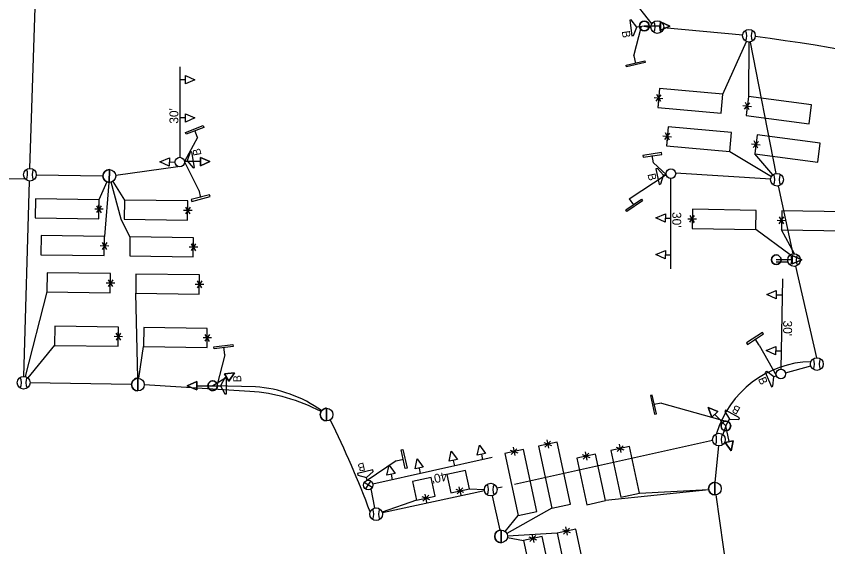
# Model space of a CAD drawing. Extents: x 596176 to 605330, y 332416 to 402398.
# Drawn here: x 604629.8 to 604885.3, y 339247.6 to 339414.6 of the extents above; entities that cross this region are included whole.
import ezdxf

# ---------------------------------------------------------------- set-up
doc = ezdxf.new("R2010")
doc.units = 0
for name, color, linetype in [('P_SIG', 7, 'Continuous'), ('P_SIG_Bold', 7, 'Continuous'), ('P_SIG_Conduit', 7, 'Continuous'), ('P_SIG_Loops', 7, 'Continuous'), ('P_SIG_SignalHeads', 7, 'Continuous')]:
    doc.layers.add(name, color=color, linetype=linetype)

# ---------------------------------------------------------------- blocks, each defined once
blk = doc.blocks.new('SIGNAL HEADS and POLES')
at = {"layer": 'P_SIG'}
blk.add_line((-15.42, 0.04), (0, 0), dxfattribs=at)
for points in [[(-24.44, 0.04), (-15.42, 4.05), (-15.42, -3.98), (-24.44, 0.04)], [(-15.42, 4.05), (-24.44, 0.04), (-15.42, -3.98), (-15.42, 4.05)]]:
    blk.add_lwpolyline(points, dxfattribs=at)
blk.add_circle((0, 0), 4.62, dxfattribs=at)
blk.add_circle((0, 0), 4.62, dxfattribs=at)
blk.add_circle((0, 0), 4.62, dxfattribs=at)
for start, end in [(0, 180), (180, 0)]:
    blk.add_arc((0, 0), 4.62, start, end, dxfattribs=at)
blk = doc.blocks.new('_U305')
at = {"layer": 'P_SIG_Loops'}
for p, q in [((-0.055, -0.084), (0.052, 0.081)), ((0.056, -0.083), (-0.053, 0.082)), ((0, 0), (0, -0.229)), ((-0.105, -0.001), (0.099, -0.001))]:
    blk.add_line(p, q, dxfattribs=at)
blk.add_lwpolyline([(0, -0.229), (1.524, -0.229), (1.524, 0.229), (0, 0.229)], close=True, dxfattribs=at)
blk = doc.blocks.new('_U309')
at = {"layer": 'P_SIG_Bold'}
for p, q in [((-3.048, 0), (-0.114, 0)), ((-0.081, 0.081), (0.081, -0.081)), ((0.081, 0.081), (-0.081, -0.081))]:
    blk.add_line(p, q, dxfattribs=at)
blk.add_circle((0, 0), 0.114, dxfattribs=at)
blk.add_text("40'", height=0.2134, dxfattribs=at).set_placement((-1.894, 0.092))
blk = doc.blocks.new('_U227')
at = {"layer": 'P_SIG'}
blk.add_circle((0, 0.01), 6.1, dxfattribs=at)
for centre, start, end in [((-15.46, 0.12), 336.67411, 22.52722), ((15.45, 0.15), 157.57508, 203.4282)]:
    blk.add_arc(centre, 13.28, start, end, dxfattribs=at)
blk = doc.blocks.new('_U226')
at = {"layer": 'P_SIG'}
blk.add_line((0.03, 6.11), (-0.03, -6.09), dxfattribs=at)
blk.add_lwpolyline([(-0.03, -6.09), (0.03, 6.11)], dxfattribs=at)
blk.add_circle((0, 0.01), 6.1, dxfattribs=at)
for start, end in [(89.70079, 180), (180, 269.70079)]:
    blk.add_arc((0, 0.01), 6.1, start, end, dxfattribs=at)
blk = doc.blocks.new('HEAD - TEMPORARY_1')
at = {"layer": 'P_SIG'}
blk.add_line((5.4, 0), (0, 0), dxfattribs=at)
blk.add_lwpolyline([(14.41, 0), (5.4, -4.01), (5.4, 4.01)], close=True, dxfattribs=at)
blk = doc.blocks.new('_U327')
at = {"layer": 'P_SIG_Bold'}
blk.add_line((-91.44, 0), (-4.57, 0), dxfattribs=at)
blk.add_circle((0, 0), 4.57, dxfattribs=at)
blk.add_text("30'", height=8.534, rotation=180.00022, dxfattribs=at).set_placement((-36.83, -1.34))
blk = doc.blocks.new('_U328')
at = {"layer": 'P_SIG_Bold'}
blk.add_line((-91.44, 0), (-4.57, 0), dxfattribs=at)
blk.add_circle((0, 0), 4.57, dxfattribs=at)
blk.add_text("30'", height=8.534, rotation=0.91967, dxfattribs=at).set_placement((-51.29, 1.4))
blk = doc.blocks.new('_U329')
at = {"layer": 'P_SIG'}
blk.add_line((-15.42, 0.04), (0, 0), dxfattribs=at)
for points in [[(-24.44, 0.04), (-15.42, 4.05), (-15.42, -3.98), (-24.44, 0.04)], [(-24.44, 0.04), (-15.42, 4.05), (-15.42, -3.98), (-24.44, 0.04)], [(-15.42, 4.05), (-24.44, 0.04), (-15.42, -3.98), (-15.42, 4.05)]]:
    blk.add_lwpolyline(points, dxfattribs=at)
blk = doc.blocks.new('_U316')
at = {"layer": 'P_SIG_Loops'}
for p, q in [((-0.055, -0.084), (0.052, 0.081)), ((0.056, -0.083), (-0.053, 0.082)), ((0, 0), (0, -0.229)), ((-0.105, -0.001), (0.099, -0.001))]:
    blk.add_line(p, q, dxfattribs=at)
blk.add_lwpolyline([(0, -0.229), (0.457, -0.229), (0.457, 0.229), (0, 0.229)], close=True, dxfattribs=at)
blk = doc.blocks.new('_U333')
at = {"layer": 'P_SIG_Loops'}
for p, q in [((-0.055, -0.084), (0.052, 0.081)), ((0.056, -0.083), (-0.053, 0.082)), ((0, 0), (0, -0.229)), ((-0.105, -0.001), (0.099, -0.001))]:
    blk.add_line(p, q, dxfattribs=at)
blk.add_lwpolyline([(0, -0.229), (1.143, -0.229), (1.143, 0.229), (0, 0.229)], close=True, dxfattribs=at)

msp = doc.modelspace()

# ---------------------------------------------------------------- linework, layer by layer
at = {"layer": 'P_SIG'}
for p, q in [((604824.24, 339402.08), (604826.68, 339411.51)), ((604827.57, 339411.51), (604825.2, 339411.17)), ((604824.24, 339402.08), (604824.78, 339399.75)), ((604686.94, 339376.41), (604686.08, 339378.65)), ((604686.94, 339376.41), (604682.8, 339368.82)), ((604830.46, 339368.39), (604830.09, 339370.76)), ((604682.78, 339368.95), (604683.67, 339369.11)), ((604687.29, 339359.82), (604682.8, 339368.82)), ((604830.46, 339368.39), (604834.49, 339364.71)), ((604822.86, 339357.14), (604834.49, 339364.71)), ((604834.49, 339364.71), (604833.61, 339364.51)), ((604687.29, 339359.82), (604687.89, 339357.5)), ((604822.86, 339357.14), (604824.22, 339355.17)), ((604863.76, 339311), (604862.45, 339313.01)), ((604863.76, 339311), (604869.19, 339301.37)), ((604695.46, 339308.03), (604692.95, 339298.25)), ((604695.46, 339308.03), (604695.16, 339310.41)), ((604869.19, 339301.37), (604868.36, 339301.01)), ((604691.7, 339298.25), (604694.11, 339298.26)), ((604832.97, 339292.82), (604830.62, 339292.3)), ((604832.97, 339292.82), (604854, 339286.92)), ((604853.25, 339285.6), (604854.43, 339287.69)), ((604749.44, 339274.64), (604751.78, 339275.15)), ((604749.44, 339274.64), (604740.34, 339268.47)), ((604740.31, 339268.47), (604740.11, 339269.35))]:
    msp.add_line(p, q, dxfattribs=at)
for points in [[(604823.48, 339413.46), (604822.97, 339413.38), (604823.67, 339408.43), (604824.19, 339408.5), (604825.2, 339411.17)], [(604821.87, 339399.21), (604827.72, 339400.57), (604827.85, 339399.98), (604822.01, 339398.63)], [(604688.88, 339379.59), (604683.29, 339377.42), (604683.07, 339377.98), (604688.67, 339380.15)], [(604685.48, 339366.9), (604685.99, 339367), (604685.07, 339371.92), (604684.56, 339371.82), (604683.67, 339369.11)], [(604827.19, 339370.17), (604833.12, 339371.1), (604833.02, 339371.69), (604827.09, 339370.76)], [(604831.72, 339366.66), (604831.22, 339366.55), (604832.29, 339361.66), (604832.8, 339361.77), (604833.61, 339364.51)], [(604690.72, 339358.37), (604684.91, 339356.87), (604685.06, 339356.29), (604690.87, 339357.79)], [(604821.71, 339353.6), (604826.65, 339357.01), (604826.99, 339356.51), (604822.05, 339353.1)], [(604860.04, 339311.29), (604865.07, 339314.56), (604864.74, 339315.07), (604859.72, 339311.79)], [(604698.11, 339310.65), (604692.15, 339309.9), (604692.08, 339310.5), (604698.03, 339311.24)], [(604695.48, 339295.76), (604696, 339295.76), (604696, 339300.76), (604695.48, 339300.76), (604694.1, 339298.26)], [(604866.11, 339302.77), (604865.63, 339302.57), (604867.61, 339297.96), (604868.08, 339298.17), (604868.36, 339301.01)], [(604831.39, 339289.45), (604830.1, 339295.31), (604829.51, 339295.18), (604830.81, 339289.32)], [(604857.29, 339287.66), (604857.55, 339288.11), (604853.19, 339290.57), (604852.93, 339290.12), (604854.43, 339287.69)], [(604752.29, 339272.24), (604750.99, 339278.1), (604751.58, 339278.22), (604752.87, 339272.36)], [(604742.24, 339271.24), (604742.12, 339271.75), (604737.24, 339270.64), (604737.36, 339270.13), (604740.11, 339269.35)]]:
    msp.add_lwpolyline(points, close=True, dxfattribs=at)
for points in [[(604823.48, 339413.46), (604822.97, 339413.38), (604823.67, 339408.43), (604824.19, 339408.5), (604825.2, 339411.17), (604823.48, 339413.46)], [(604685.48, 339366.9), (604685.99, 339367), (604685.07, 339371.92), (604684.56, 339371.82), (604683.67, 339369.11), (604685.48, 339366.9)], [(604831.72, 339366.66), (604831.22, 339366.55), (604832.29, 339361.66), (604832.8, 339361.77), (604833.61, 339364.51), (604831.72, 339366.66)], [(604695.48, 339295.76), (604696, 339295.76), (604696, 339300.76), (604695.48, 339300.76), (604694.1, 339298.26), (604695.48, 339295.76)], [(604866.11, 339302.77), (604865.63, 339302.57), (604867.61, 339297.96), (604868.08, 339298.17), (604868.36, 339301.01), (604866.11, 339302.77)], [(604857.29, 339287.66), (604857.55, 339288.11), (604853.19, 339290.57), (604852.93, 339290.12), (604854.43, 339287.69), (604857.29, 339287.66)], [(604742.24, 339271.24), (604742.12, 339271.75), (604737.24, 339270.64), (604737.36, 339270.13), (604740.11, 339269.35), (604742.24, 339271.24)]]:
    msp.add_lwpolyline(points, dxfattribs=at)
at = {"layer": 'P_SIG_Conduit'}
for p, q in [((604634.12, 339366.68), (604636, 339425.66)), ((604820.19, 339424.52), (604829.9, 339412.1)), ((604827.57, 339411.51), (604829.68, 339411.02)), ((604833.67, 339411), (604858.55, 339408.73)), ((604661.13, 339364.51), (604680.7, 339367.3)), ((604636.12, 339364.65), (604657.14, 339364.31)), ((604632.21, 339301.2), (604634, 339362.69)), ((604869.11, 339337.28), (604872.8, 339337.27)), ((604872.01, 339302.36), (604879.97, 339304.55)), ((604666.14, 339298.66), (604634.15, 339299.17)), ((604853.25, 339285.6), (604852.27, 339282.91)), ((604779.65, 339263.6), (604782.07, 339252.77))]:
    msp.add_line(p, q, dxfattribs=at)
for points in [[(604860.94, 339406.46), (604868.98, 339365.07)], [(604632.71, 339363.27), (604490.54, 339364.68), (604473.91, 339363.18)], [(604867.36, 339363.24), (604837.44, 339365.21)], [(604869.74, 339361.15), (604874.37, 339339.8)], [(604875.17, 339335.88), (604881.8, 339307.08)], [(604703.39, 339296.47), (604670.14, 339298.51)], [(604705.12, 339297.93), (604691.9, 339298.22)], [(604849.09, 339281.03), (604786.69, 339267.21)], [(604849.86, 339267.86), (604851.06, 339279.31)], [(604742.76, 339259.79), (604741.56, 339265.82)], [(604777.26, 339265.16), (604745.11, 339258.25)], [(604782.78, 339266.35), (604781.17, 339266)], [(604850.05, 339263.88), (604853.59, 339239.38)]]:
    msp.add_lwpolyline(points, dxfattribs=at)
for centre, radius, start, end in [((604792.07, 338853.66), 558.97, 67.1324, 82.7601), ((604880.74, 339274.14), 31.7, 91.2514, 163.4396), ((604702.35, 339257.55), 40.47, 54.3067, 86.0731), ((604699.58, 339240.2), 56.4, 62.3143, 86.1247), ((604425.66, 339139.11), 337.45, 20.7234, 26.0982), ((604880.74, 339274.14), 31.7, 169.3989, 169.5784)]:
    msp.add_arc(centre, radius, start, end, dxfattribs=at)
at = {"layer": 'P_SIG_Loops'}
for p, q in [((604852.29, 339390.03), (604859.71, 339406.59)), ((604860.52, 339406.42), (604860.37, 339389.3)), ((604854.48, 339371.97), (604867.64, 339364.13)), ((604868.05, 339364.62), (604862.33, 339371.26)), ((604658.34, 339362.45), (604655.88, 339356.81)), ((604658.98, 339362.29), (604657.63, 339345.23)), ((604662.88, 339350.68), (604659.67, 339362.35)), ((604660.2, 339362.59), (604663.88, 339356.7)), ((604665.63, 339345.12), (604662.88, 339350.68)), ((604873.52, 339339.43), (604862.65, 339347.47)), ((604874.9, 339339.82), (604870.77, 339347.33)), ((604639.44, 339327.82), (604632.66, 339301.14)), ((604668.09, 339300.63), (604667.44, 339327.42)), ((604641.9, 339310.98), (604633.44, 339300.74)), ((604668.43, 339300.61), (604669.9, 339310.58)), ((604772.5, 339265.77), (604777.22, 339265.62)), ((604847.84, 339265.5), (604815.32, 339262.08)), ((604826.07, 339264.45), (604847.82, 339265.6)), ((604755.86, 339262.22), (604745.04, 339258.48)), ((604798.45, 339259.69), (604784.25, 339251.79)), ((604783.77, 339252.36), (604787.86, 339257.36)), ((604800.14, 339251.87), (604784.5, 339250.93)), ((604784.47, 339250.46), (604789.55, 339249.54))]:
    msp.add_line(p, q, dxfattribs=at)

# ---------------------------------------------------------------- block references
at = {"layer": 'P_SIG'}
for name, p, xscale, yscale, rotation in [('SIGNAL HEADS and POLES', (604827.57, 339411.51), 0.32808333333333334, 0.32808333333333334, 180), ('_U327', (604681.31, 339368.67), 0.3280833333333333, 0.3280833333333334, -90.00022331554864), ('_U329', (604682.8, 339368.82), 0.32808333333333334, 0.32808333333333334, 180), ('_U327', (604835.95, 339365.03), 0.3280833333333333, 0.3280833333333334, 89.9997766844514), ('SIGNAL HEADS and POLES', (604869.12, 339337.92), 0.32808333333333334, 0.32808333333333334, 180), ('_U328', (604870.57, 339301.96), 0.3280833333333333, 0.32808333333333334, -90.91966715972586), ('SIGNAL HEADS and POLES', (604691.7, 339298.25), 0.32808333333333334, 0.3280833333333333, -149.23830530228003), ('SIGNAL HEADS and POLES', (604853.25, 339285.6), 0.32808333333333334, 0.32808333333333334, -46.038730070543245), ('SIGNAL HEADS and POLES', (604853.25, 339285.6), 0.32808333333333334, 0.3280833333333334, 102.23408685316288), ('_U309', (604740.64, 339267), 13.123333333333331, 13.123333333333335, -167.5414512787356)]:
    msp.add_blockref(name, p, dxfattribs=dict(at, xscale=xscale, yscale=yscale, rotation=rotation))
at = {"layer": 'P_SIG', "xscale": 0.32808333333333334, "yscale": 0.32808333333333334}
msp.add_blockref('SIGNAL HEADS and POLES', (604691.7, 339298.25), dxfattribs=at)
at = {"layer": 'P_SIG_Conduit', "xscale": 0.32808333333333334, "yscale": 0.32808333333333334}
for name, p in [('_U227', (604831.67, 339411.17)), ('_U227', (604860.53, 339408.42)), ('_U227', (604634.12, 339364.68)), ('_U226', (604659.14, 339364.28)), ('_U227', (604869.36, 339363.11)), ('_U227', (604874.72, 339337.83)), ('_U227', (604881.9, 339305.08)), ('_U227', (604632.16, 339299.2)), ('_U226', (604668.14, 339298.63)), ('_U226', (604727.54, 339289.18)), ('_U227', (604851.07, 339281.31)), ('_U227', (604779.22, 339265.55)), ('_U226', (604849.81, 339265.86)), ('_U227', (604743.15, 339257.82)), ('_U226', (604782.5, 339250.81))]:
    msp.add_blockref(name, p, dxfattribs=at)
at = {"layer": 'P_SIG_Loops'}
for name, p, xscale, yscale, rotation in [('_U305', (604832.1, 339388.86), 13.12333333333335, 13.123333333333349, -5.188945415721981), ('_U305', (604859.99, 339386.32), 13.123333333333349, 13.123333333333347, -7.423319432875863), ('_U305', (604834.83, 339376.77), 13.12333333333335, 13.123333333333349, -5.188945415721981), ('_U305', (604862.72, 339374.23), 13.123333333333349, 13.123333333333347, -7.423319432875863), ('_U305', (604655.84, 339353.81), 13.12333333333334, 13.12333333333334, 179.19388611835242), ('_U305', (604683.83, 339353.42), 13.12333333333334, 13.12333333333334, 179.19388611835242), ('_U305', (604842.7, 339350.8), 13.12333333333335, 13.123333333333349, -0.9548804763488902), ('_U305', (604870.82, 339350.33), 13.12333333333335, 13.123333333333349, -0.9548804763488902), ('_U305', (604657.59, 339342.23), 13.12333333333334, 13.12333333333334, 179.19388611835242), ('_U305', (604685.58, 339341.84), 13.12333333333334, 13.12333333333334, 179.19388611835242), ('_U305', (604659.48, 339330.54), 13.123333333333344, 13.123333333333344, 179.19388611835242), ('_U305', (604687.48, 339330.14), 13.123333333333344, 13.123333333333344, 179.19388611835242), ('_U305', (604661.94, 339313.7), 13.123333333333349, 13.123333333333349, 179.19388611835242), ('_U305', (604689.94, 339313.3), 13.123333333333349, 13.123333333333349, 179.19388611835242), ('_U305', (604797.16, 339279.87), 13.123333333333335, 13.123333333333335, -77.81394907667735), ('_U333', (604819.97, 339278.48), 13.123333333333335, 13.123333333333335, -77.81394907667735), ('_U305', (604786.58, 339277.54), 13.123333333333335, 13.123333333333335, -77.81394907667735), ('_U333', (604809.23, 339276.11), 13.123333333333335, 13.123333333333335, -77.81394907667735), ('_U316', (604769.57, 339265.13), 13.123333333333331, 13.123333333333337, 102.18605092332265), ('_U316', (604758.79, 339262.85), 13.123333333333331, 13.123333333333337, 102.18605092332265), ('_U305', (604803.07, 339252.51), 13.123333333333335, 13.123333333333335, -77.81394907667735), ('_U305', (604792.49, 339250.17), 13.123333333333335, 13.123333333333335, -77.81394907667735)]:
    msp.add_blockref(name, p, dxfattribs=dict(at, xscale=xscale, yscale=yscale, rotation=rotation))
at = {"layer": 'P_SIG_SignalHeads', "xscale": 0.32808333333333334, "yscale": 0.32808333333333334}
for p in [(604681.31, 339394.57), (604681.31, 339382.59)]:
    msp.add_blockref('HEAD - TEMPORARY_1', p, dxfattribs=at)
at = {"layer": 'P_SIG_SignalHeads', "xscale": 0.32808333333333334}
for p, yscale, rotation in [((604679.81, 339368.67), 0.3280833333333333, 179.08348304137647), ((604835.95, 339351), 0.3280833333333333, 179.08348304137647), ((604835.95, 339339.45), 0.3280833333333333, 179.08348304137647), ((604870.86, 339326.89), 0.3280833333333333, 179.08348304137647), ((604870.69, 339309.23), 0.3280833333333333, 179.08348304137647), ((604767.8, 339273.01), 0.3280833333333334, 102.30178657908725), ((604776.66, 339274.96), 0.3280833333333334, 102.30178657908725), ((604757.04, 339270.63), 0.3280833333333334, 102.30178657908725), ((604748.2, 339268.67), 0.3280833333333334, 102.30178657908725)]:
    msp.add_blockref('HEAD - TEMPORARY_1', p, dxfattribs=dict(at, yscale=yscale, rotation=rotation))

# ---------------------------------------------------------------- texts
at = {"layer": 'P_SIG'}
for rotation, p in [(278.1202, (604820.48, 339409.84)), (100.5576, (604688.15, 339370.94)), (282.4346, (604828.56, 339364.82)), (90.0968, (604700.67, 339299.35)), (293.2022, (604863.34, 339300.37)), (150.5017, (604858.04, 339291.24)), (192.8589, (604739.34, 339274.12))]:
    msp.add_text('B', height=2.52, rotation=rotation, dxfattribs=at).set_placement(p)

doc.saveas('drawing.dxf')
